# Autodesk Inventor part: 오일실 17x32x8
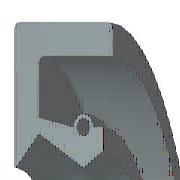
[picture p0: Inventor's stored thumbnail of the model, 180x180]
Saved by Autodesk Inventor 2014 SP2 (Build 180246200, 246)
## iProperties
IsCustomPart: 1
Company: 한국ATC센터
Created: 2014-07
Part Number: 오일실 17x32x8
Material: 고무
Description: 오일-실
Document SubType Name: Modeling
Standard: KS B 2804
Designer: KYOUNG IL JANG
Standards Organization: KS
Language: ko-KR
Size Designation: D - 17 32 8
Categories: <MemberInstance><Categories><Category DisplayName="샤프트 부품" InternalName="7f7aeb1f-a693-4053-b835-cee3144e0d98" Mnemonic="SHFT"><Category DisplayName="실링" Intern
Density: 0.93 g/cm^3
Appearance: 고무 - 검은색 - 버전 1.1
Author: KYOUNG IL JANG
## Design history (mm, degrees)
revolve "본체" stored, may be unused: angle "d17" = 90 deg
revolve "스프링1" stored, may be unused: angle "d18" = 90 deg
body "Solid1"
sketch "스케치1"
  geometry: L1 (0, 16)-(8, 16); L2 (8, 14.25)-(1.75, 14.25); L3 (1.75, 10.25)-(4.9, 8.5); L4 (4.9, 8.5)-(0, 8.5); L5 (0, 0)-(9.586, 0) reference; L6 (4.9, 8.5)-(6.3, 9.375); L7 (0, 18)-(0, -3) reference; L8 (-1.941, 0)-(11.507, 0) reference; L9 (4.2, 10.6)-(1.75, 11.21); L10 (1.75, 11.21)-(1.75, 14.25); L11 (0, 16)-(0, 8.588); L12 (4.9, 8.5)-(0, 8.5); L13 (1.75, 10.25)-(0.152, 8.528); L14 (8, 16)-(8, 14.25); L15 (5.6, 10.6)-(6.3, 10.6); L16 (6.3, 10.6)-(6.3, 9.375); C1 r 0.455 at (4.9, 10.6); A1 r 0.7 centre (4.9, 10.6) between (5.6, 10.6) and (4.2, 10.6); A2 r 0.088 centre (0.088, 8.588) between (0, 8.588) and (0.152, 8.528); 1 further point
  constraints: 28 end point, 5 horizontal alignment, 5 point on line, 4 point on circle, 4 vertical alignment, 3 centre point, 3 tangent, 2 collinear, 2 horizontal, 2 perpendicular, 1 coincident, 1 parallel
  dimensions: "d0" = 32 diameter of L1 L5 (= SD2); "d1" = 1.75 distance of L1.end L2.start (= SD); "d2" = 0.91 diameter of C1 (= SPDI); "d3" = 1.4 diameter of A1 (= SPDA); "d4" = 17 diameter of L3.end L5 (= NND); "d5" = 20.5 diameter of L3.start L5 (= TKDM); "d7" = 22.42 diameter of L9.end L5 (= TKDM + 0.24 x SWDT); "d8" = 1.75 distance between parallel lines of L11 L10 (= SD); "d9" = 4.9 distance from line of L11 C1.centre (= SPDST); "d10" = 21.2 diameter of C1.centre L5 (= HLDM); "d11" = 0.0875 radius of A2 (= 0.25 x LAB); "d12" = 6.3 distance between parallel lines of L11 L16 (= SDI); "d13" = 18.75 diameter of L6.end L5 (= ABDM); "d14" = 8 distance from line of L11 L1.end (= SWDT)
fillet "모깎기1" dims "d6" = 0.3 (= RR)
other parameters: "SD2" = 32 [user parameter; used in 1 equation term], "SWDT" = 8 [user parameter; used in 2 equation terms], "RR" = 0.3 [user parameter; used in 1 equation term], "SD" = 1.75 [user parameter; used in 2 equation terms], "NND" = 17 [user parameter; used in 1 equation term], "SPDA" = 1.4 [user parameter; used in 1 equation term], "SPDI" = 0.91 [user parameter; used in 1 equation term], "TKDM" = 20.5 [user parameter; used in 2 equation terms], "HLDM" = 21.2 [user parameter; used in 1 equation term], "ABDM" = 18.75 [user parameter; used in 1 equation term], "SDI" = 6.3 [user parameter; used in 1 equation term], "SPDST" = 4.9 [user parameter; used in 1 equation term], "LAB" = 0.35 [user parameter; used in 1 equation term], "d15" = 0, "d16" = 0, "d19" = 0
